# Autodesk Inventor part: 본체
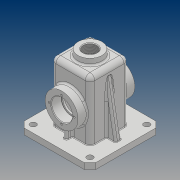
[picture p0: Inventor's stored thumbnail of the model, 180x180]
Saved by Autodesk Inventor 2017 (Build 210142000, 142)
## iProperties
Part Number: 본체
Material: 일반
Document SubType Name: Modeling
Designer: 20
Density: 1 g/cm^3
Appearance: 기본값
Mass: 293.223 g
Surface Area: 897.811 cm^2
Volume: 293.223 cm^3
Author: 20
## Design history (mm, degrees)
sketch "스케치1"
  geometry: L1 (-32.5, -32.5)-(32.5, -32.5); L2 (32.5, -32.5)-(32.5, 32.5); L3 (32.5, 32.5)-(-32.5, 32.5); L4 (-32.5, 32.5)-(-32.5, -32.5); L5 (-32.5, -32.5)-(32.5, 32.5); L6 (32.5, -32.5)-(-32.5, 32.5); 1 further point
  constraints: 12 end point, 2 midpoint, 2 parallel, 1 horizontal, 1 perpendicular
  dimensions: "d0" = 65 distance of L3.end L2.end; "d1" = 65 distance of L2.end L1.end
extrude "돌출1" new body sketch "스케치1" distance "d2" = 110; taper "d3" = 0 deg
feature "쉘1" dims "d4" = 5
sketch "스케치2"
  geometry: L1 (60, 60)-(-60, 60); L2 (-60, 60)-(-60, -60); L3 (-60, -60)-(60, -60); L4 (60, -60)-(60, 60); L5 (60, 60)-(-60, -60); L6 (-60, 60)-(60, -60); L7 (27.5, -27.5)-(-27.5, -27.5) reference; L8 (27.5, 27.5)-(27.5, -27.5) reference; L9 (-27.5, 27.5)-(27.5, 27.5) reference; L10 (-27.5, -27.5)-(-27.5, 27.5) reference; 1 further point
  constraints: 12 end point, 2 midpoint, 2 parallel, 1 horizontal, 1 perpendicular
  dimensions: "d5" = 120 distance of L3.end L2.end; "d6" = 120 distance of L2.end L1.end
extrude "돌출2" join sketch "스케치2" distance "d7" = 10; taper "d8" = 0 deg
sketch "스케치4"
  geometry: C1 r 27.5 at (0, 55); 1 further point
  constraints: 1 centre point, 1 vertical alignment
  dimensions: "d9" = 55 diameter of C1; "d10" = 55 distance of point (0, 0) C1.centre
extrude "돌출3" join sketch "스케치4" stored distance "d11" = 95; taper "d12" = 0 deg
sketch "스케치5"
  geometry: L1 (-27.5, -27.5)-(-27.5, 27.5) reference; L2 (27.5, -27.5)-(-27.5, -27.5) reference; L3 (27.5, 27.5)-(27.5, -27.5) reference; L4 (-27.5, 27.5)-(27.5, 27.5) reference; 1 further point
extrude "돌출4" cut sketch "스케치5" distance "d13" = 100; taper "d14" = 0 deg
sketch "스케치6"
  geometry: C1 r 20 at (0, 0); 1 further point
  constraints: 1 centre point, 1 coincident
  dimensions: "d15" = 40 diameter of C1
extrude "돌출5" join sketch "스케치6" distance "d16" = 10; taper "d17" = 0 deg
sketch "스케치7"
  geometry: C1 r 17.5 at (0, 0); C2 r 27.5 at (0, 0) reference; 1 further point
  constraints: 1 centre point, 1 concentric
  dimensions: "d19" = 35 diameter of C1
extrude "돌출6" cut sketch "스케치7" distance "d20" = 17; taper "d21" = 0 deg
sketch "스케치8"
  geometry: C1 r 15 at (0, 0); C2 r 17.5 at (0, 0) reference; 1 further point
  constraints: 1 centre point, 1 concentric
  dimensions: "d22" = 30 diameter of C1
extrude "돌출7" cut sketch "스케치8" distance "d23" = 3; taper "d24" = 0 deg
sketch "스케치9"
  geometry: L1 (-27.5, -27.5)-(27.5, -27.5) reference; L2 (-3, -27.5)-(3, -27.5); L3 (3, -27.5)-(3, -42.5); L4 (3, -42.5)-(-3, -42.5); L5 (-3, -42.5)-(-3, -27.5); 1 further point
  constraints: 8 end point, 2 parallel, 1 horizontal, 1 perpendicular, 1 point on line
  dimensions: "d25" = 6 distance between parallel lines of L3 L5; "d26" = 3 distance from line of point (0, 0) L5; "d27" = 15 distance between parallel lines of L1 L4
extrude "돌출8" join sketch "스케치9" stored distance "d28" = 3; taper "d29" = 0 deg
sketch "스케치10"
  geometry: L1 (-60, 10)-(60, 10) reference; L2 (48, 10)-(39.184, 60); L3 (60, 0)-(60, 10) reference; 1 further point
  constraints: 2 end point, 1 point on line
  dimensions: "d30" = 12 distance from line of L3 L2.start; "d31" = 10 deg angle of L3 L2; "d32" = 50 vertical distance of L2.start L2.end
feature "리브1" sketch "스케치10" dims "d33" = 1, "d34" = 10, "d35" = 0, "d36" = 0, "d37" = 1, "d38" = 1
hole "구멍1" diameter "d41" = 22.835; stored, may be unused: countersink angle "d45" = 90 deg, drill point angle "d47" = 118 deg; dims "d39" = 10, "d40" = 10, "d42" = 50, "d43" = 4, "d44" = 2, "d46" = 30
sketch "스케치11"
  geometry: C1 r 5 at (-47.5, 47.5); 1 further point
  constraints: 1 centre point
  dimensions: "d48" = 10 diameter of C1; "d51" = 47.5 horizontal distance of point (0, 0) C1.centre; "d52" = 47.5 horizontal distance of point (0, 0) C1.centre
extrude "돌출9" cut sketch "스케치11" stored distance "d53" = 3; taper "d54" = 0 deg
chamfer "모따기1" distance "d61" = 10; stored, may be unused: second distance "d62" = 2, angle "d63" = 45 deg
sketch "스케치12"
  geometry: C1 r 27.5 at (0, 0) reference; 2 further points
  constraints: 1 vertical alignment
  dimensions: "d64" = 21 distance of C1.centre point (0, 21)
hole "구멍2" sketch "스케치12" at (0, 21) diameter "d65" = 3.242; stored, may be unused: countersink angle "d69" = 90 deg, drill point angle "d71" = 118 deg; dims "d66" = 8, "d67" = 4, "d68" = 2, "d70" = 10
fillet "모깎기1" dims "d75" = 8
fillet "모깎기2" dims "d76" = 8
fillet "모깎기3" dims "d77" = 3
fillet "모깎기4" dims "d78" = 3
fillet "모깎기5" dims "d79" = 3
fillet "모깎기6" dims "d80" = 3
fillet "모깎기7" dims "d81" = 3
fillet "모깎기9" dims "d83" = 1
chamfer "모따기2" distance "d84" = 1; stored, may be unused: second distance "d85" = 2, angle "d86" = 45 deg
fillet "모깎기10" dims "d87" = 3
fillet "모깎기11" dims "d88" = 0.3
node "작업 평면1"
sketch "스케치13"
  geometry: L1 (-32.5, 102)-(-32.5, 11) reference; L2 (20, 120)-(-20, 120) reference; 2 further points
  constraints: 1 other
  dimensions: "d90" = 32.5 distance from line of point (0, 94) L1; "d91" = 26 distance from line of point (0, 94) L2
feature "엠보싱1" sketch "스케치13" dims "d92" = 0.5, "d93" = 0
feature "면 기울기2" dims angle "d94" = 5 deg
fillet "모깎기12" dims "d95" = 3
node "솔리드1"
mirror "미러1"
mirror "미러2"
mirror "미러3"
pattern_linear "직사각형 패턴1" dims "d57" = 95, "d60" = 95
pattern_circular "원형 패턴1" dims angle "d73" = 360 deg
mirror "미러4"
